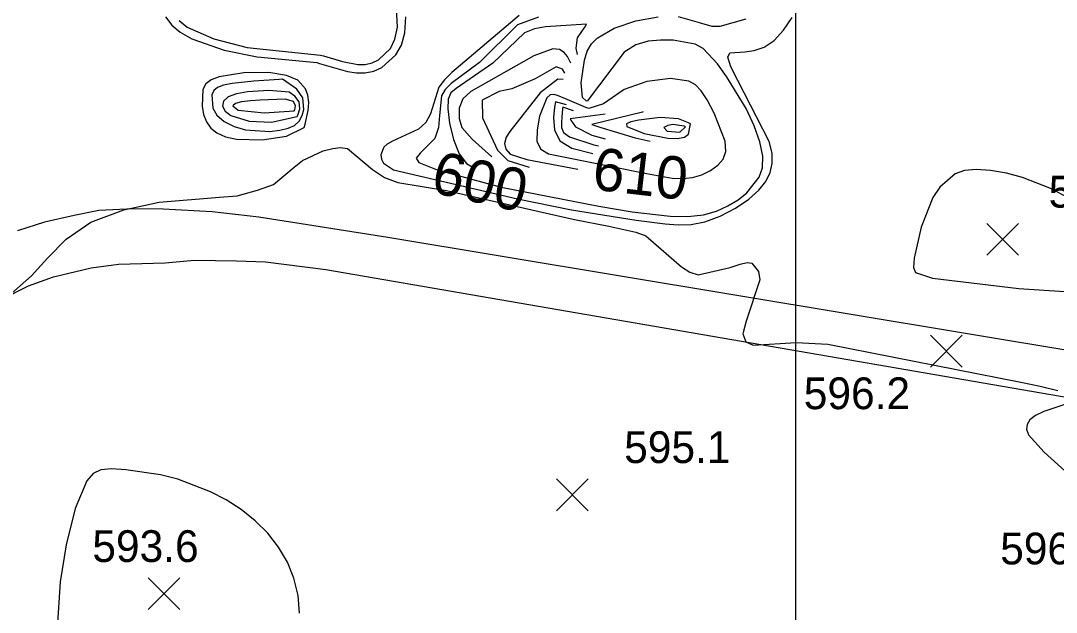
# Model space of a CAD drawing. Extents: x 79600 to 91800, y 75600 to 84400.
# Drawn here: x 86334.2 to 86823, y 76116.3 to 76395.7 of the extents above; entities that cross this region are included whole.
import ezdxf

# ---------------------------------------------------------------- set-up
doc = ezdxf.new("R2010")
doc.units = 0
for name, color, linetype in [('080-085$0$TI_BORDER', 7, 'Continuous'), ('080-090$0$INDEX', 7, 'Continuous'), ('080-090$0$INDXLBL', 7, 'Continuous'), ('080-090$0$INTER', 7, 'Continuous'), ('080-090$0$ROAD', 7, 'Continuous'), ('080-090$0$SPOTMARK', 7, 'Continuous'), ('080-090$0$SPOTS', 7, 'Continuous')]:
    doc.layers.add(name, color=color, linetype=linetype)

# ---------------------------------------------------------------- blocks, each defined once
blk = doc.blocks.new('080-090$0$SPOTS')
at = {"layer": '080-090$0$SPOTMARK'}
for p, q in [((-0.5, -0.5), (0.5, 0.5)), ((-0.5, 0.5), (0.5, -0.5))]:
    blk.add_line(p, q, dxfattribs=at)

msp = doc.modelspace()

# ---------------------------------------------------------------- linework, layer by layer
at = {"layer": '080-085$0$TI_BORDER'}
msp.add_lwpolyline([(79700, 80300), (86700, 80300), (86700, 75700), (79700, 75700)], close=True, dxfattribs=at)
at = {"layer": '080-090$0$INDEX'}
for points in [[(86409.09, 76395.76), (86412.88, 76392.65), (86425.34, 76387.09), (86441.16, 76382.97), (86475.78, 76379.44), (86477.09, 76379.04), (86486.19, 76376.41), (86493.34, 76375.07), (86496.78, 76375.06), (86500.07, 76375.74), (86503.19, 76377.17), (86508.79, 76382.62), (86510.89, 76386.93), (86512.08, 76392.59), (86511.37, 76407.51)], [(86578.64, 76397.37), (86568.81, 76393.78), (86550.85, 76376.01), (86537.41, 76365.95), (86534.61, 76363.24), (86532.89, 76360.14), (86531.86, 76350.9), (86531.39, 76345.2), (86529.73, 76339.99), (86522.85, 76333.07), (86520.95, 76330.76), (86522.12, 76328.71), (86530.79, 76325.21), (86561.1, 76317.03), (86607.15, 76308.07), (86622.85, 76305.48), (86640.74, 76303.38), (86649.21, 76303.22), (86656.5, 76304.06), (86662.7, 76305.79), (86668.07, 76308.21), (86672.82, 76311.14), (86676.92, 76314.46), (86682.87, 76321.85), (86684.35, 76326.25), (86684.49, 76331.68), (86683.1, 76338.42), (86680.37, 76346.1), (86676.59, 76354.18), (86667.46, 76369.38), (86663.2, 76375.37), (86656.4, 76382.63), (86652.62, 76384.54), (86642.24, 76386.41), (86636.29, 76386.51), (86630.35, 76386), (86624.57, 76384.34), (86619.05, 76380.89), (86601.69, 76357.7), (86601.19, 76357.83), (86599.42, 76359.38), (86598.8, 76366.4), (86600.35, 76377.06), (86601.69, 76381.34), (86603.59, 76384.7), (86606.29, 76387.47), (86614.43, 76392.11), (86624.64, 76395.58), (86635.14, 76397.57)], [(86644.59, 76397.63), (86654.46, 76394.8), (86660.39, 76393.07), (86664.42, 76393.11), (86676.63, 76396.53)]]:
    msp.add_lwpolyline(points, dxfattribs=at)
for points in [[(86456.18, 76367.95), (86444.2, 76367.19), (86434.11, 76365.98), (86429.99, 76365.16), (86427.1, 76364.17), (86425.32, 76362.77), (86424.4, 76360.7), (86424.86, 76354.4), (86426.84, 76351.01), (86430.33, 76348.05), (86435.01, 76345.71), (86440.41, 76344.12), (86451.61, 76343.37), (86456.52, 76343.91), (86460.47, 76344.85), (86463.49, 76346.26), (86465.68, 76348.25), (86467.15, 76350.83), (86467.91, 76353.74), (86467.36, 76359.2), (86464.6, 76363.4), (86457.83, 76367.99)], [(86600.92, 76354.74), (86592.18, 76358.4), (86587.59, 76360.37), (86585.84, 76360.79), (86584.2, 76360.61), (86582.57, 76359.23), (86579.15, 76350.55), (86577.94, 76344.21), (86577.92, 76338.59), (86579.67, 76334.94), (86583.34, 76332.8), (86613.99, 76326.67), (86629.6, 76323.44), (86641.77, 76321.33), (86646.75, 76321.09), (86651.36, 76321.6), (86655.77, 76322.96), (86659.82, 76324.99), (86663.25, 76327.47), (86665.79, 76330.29), (86667.08, 76333.86), (86666.76, 76338.73), (86661.52, 76352.08), (86658.2, 76358.24), (86655.37, 76362.62), (86652.71, 76365.4), (86649.63, 76367.07), (86640.9, 76368.32), (86629.75, 76366.92), (86619.07, 76363.23), (86609.36, 76356.49), (86602.34, 76354.19)], [(86649.39, 76347.49), (86644.75, 76349.39), (86636.12, 76350.02), (86626.08, 76348.73), (86622.24, 76347.9), (86620.11, 76346.94), (86620.4, 76345.68), (86628.51, 76342.4), (86639.65, 76340.13), (86644.22, 76339.98), (86647.58, 76340.66), (86649.51, 76342.13), (86650.35, 76346.92)]]:
    msp.add_lwpolyline(points, close=True, dxfattribs=at)
at = {"layer": '080-090$0$INTER'}
for points in [[(86402.6, 76397.57), (86405.51, 76393.63), (86409.54, 76390.21), (86415.04, 76387.13), (86430.25, 76381.81), (86445.78, 76378.65), (86474.02, 76375.93), (86475.27, 76375.5), (86488.48, 76371.64), (86492.68, 76371.04), (86496.86, 76371.05), (86500.9, 76371.87), (86504.7, 76373.54), (86511.37, 76379.51), (86513.9, 76384.07), (86515.53, 76390.02), (86516.06, 76397.49)], [(86569.58, 76398.12), (86537.8, 76371.25), (86534.28, 76367.81), (86531.6, 76364.35), (86527.59, 76351.63), (86525.54, 76347.56), (86521.97, 76344.38), (86509.75, 76338.75), (86507.26, 76337.42), (86505.59, 76335.97), (86504.3, 76332.31), (86504.6, 76330.33), (86505.54, 76328.43), (86510.2, 76325.17), (86568.8, 76311.5), (86594.26, 76306.31), (86624.79, 76301.52), (86638.46, 76299.77), (86644.6, 76299.26), (86650.68, 76299.42), (86657.18, 76300.71), (86664.36, 76303.41), (86671.57, 76307.14), (86677.9, 76311.35), (86682.65, 76315.58), (86685.91, 76319.78), (86687.96, 76323.98), (86689, 76328.3), (86688.94, 76333.05), (86687.6, 76338.58), (86672.78, 76367.43), (86669.44, 76373.85), (86667.94, 76378.39), (86668.93, 76380.49), (86675.98, 76380.99), (86680.5, 76381.56), (86685.18, 76383.21), (86689.85, 76386.33), (86694.32, 76391.15), (86698.34, 76397.13)], [(86597.13, 76379.67), (86596.41, 76382.67), (86597.02, 76387.64), (86600.56, 76392.68), (86601.24, 76394.11), (86581.92, 76392.72), (86576.74, 76391.86), (86572.05, 76389.99), (86557.04, 76375.63), (86539.79, 76363.68), (86537.22, 76361.54), (86535.99, 76358.67), (86535.88, 76354.11), (86536.71, 76347.31), (86538.46, 76339.62), (86541.12, 76332.83), (86544.67, 76328.29), (86547.27, 76326.61)], [(86593.98, 76375.61), (86592.34, 76378.77), (86590.79, 76380.73), (86588.52, 76382.14), (86585.39, 76382.39), (86576.51, 76379.12), (86546.63, 76362.29), (86542.86, 76358.84), (86541.15, 76354.35), (86541.18, 76349.5), (86542.44, 76345.25), (86547.27, 76339.8), (86556.59, 76331.37)], [(86591.08, 76370.87), (86589.92, 76372.79), (86587.03, 76373.88), (86577, 76368.17), (86565.98, 76363.57), (86560.06, 76362.23), (86552.02, 76358.16), (86552.28, 76349.83), (86559.27, 76334.53), (86564.1, 76329.69), (86574.17, 76326.56)], [(86590.32, 76367.86), (86587.82, 76368.07), (86579.48, 76361.61), (86565.16, 76343.29), (86563.35, 76340.6), (86562.67, 76337.73), (86563.28, 76334.97), (86565.25, 76332.67), (86573.14, 76330.06), (86597.16, 76325.49)], [(86591.82, 76355.9), (86586.6, 76357.42), (86586.2, 76354.78)], [(86586.2, 76354.78), (86585.73, 76349.98), (86586.17, 76344.19), (86588.76, 76338.95), (86594.32, 76335.41), (86604.35, 76333.03)], [(86590, 76354.03), (86589.61, 76350.12), (86589.45, 76347.65), (86589.52, 76345.2), (86590.52, 76342.88), (86593.23, 76340.77), (86604.83, 76337.09), (86606.92, 76336.59)], [(86595.22, 76353.15), (86590.14, 76354.92), (86590, 76354.03)], [(86628.06, 76352.57), (86627.7, 76352.54), (86603.75, 76346.65), (86607.65, 76345.33)], [(86610.13, 76351.57), (86593.61, 76349.34), (86593.83, 76348.63)], [(86593.83, 76348.63), (86596.04, 76345.56), (86603.88, 76341.6), (86610.11, 76339.87)], [(86607.65, 76345.33), (86624.35, 76340.39), (86631.37, 76338.79)], [(86317.81, 76256.21), (86339.39, 76275.16), (86346.88, 76283.57), (86355.66, 76292.52), (86367.4, 76300.49), (86382.92, 76306.29), (86399.52, 76309.97), (86428.03, 76312.33), (86436.45, 76313.03), (86445.96, 76315.58), (86453.51, 76318.28), (86463.28, 76326.46), (86467.28, 76329.64), (86477.01, 76334.16), (86481.58, 76335.39), (86485.25, 76335.87), (86488.43, 76335.28), (86500.36, 76325.45), (86505.93, 76321.68), (86512.31, 76319.25), (86535.19, 76315.48), (86595.67, 76301.79), (86611.84, 76298.56), (86624.66, 76295.75), (86629.26, 76294.09), (86646.22, 76279.49), (86650.07, 76276.85), (86653.99, 76275.61), (86669.1, 76279.07), (86673.78, 76280.75), (86677.11, 76281.51), (86679.36, 76281.2), (86682.44, 76277.22), (86683.07, 76273.33), (86676.59, 76253.81), (86675.1, 76247.8), (86676.44, 76244.08), (86679.97, 76242.38), (86700.26, 76243.77), (86715.29, 76242.98), (86806.27, 76224.97), (86815.51, 76223.02), (86823.78, 76221.04)], [(86832.97, 76309.59), (86820.8, 76316.21), (86807.16, 76321.61), (86799.56, 76323.6), (86792.01, 76324.92), (86785.24, 76325.41), (86779.78, 76324.91), (86775.38, 76323.38), (86768.06, 76317.12), (86764.78, 76312.18), (86759.31, 76298.09), (86756.02, 76283.53), (86755.58, 76279.19), (86756.52, 76276.69), (86764.58, 76274.06), (86805.38, 76269.22), (86846.15, 76266.52)], [(86834.93, 76217.01), (86817.23, 76211.16), (86813.17, 76209.2), (86810.61, 76207.15), (86809.26, 76205.01), (86808.96, 76202.76), (86809.97, 76200.07), (86817.37, 76191.94), (86837.01, 76174.08)], [(86465.89, 76115.78), (86465.15, 76124.26), (86463.2, 76132.36), (86460.11, 76140), (86455.95, 76147.1), (86450.85, 76153.63), (86444.94, 76159.52), (86438.36, 76164.75), (86431.28, 76169.31), (86423.85, 76173.21), (86408.35, 76179.07), (86400.19, 76181.14), (86383.85, 76183.63), (86377.1, 76183.96), (86372.09, 76183.51), (86368.42, 76181.81), (86365.43, 76178.32), (86359.95, 76165.35), (86355.63, 76148.17), (86352.88, 76130.65), (86350.75, 76098.97)]]:
    msp.add_lwpolyline(points, dxfattribs=at)
for points in [[(86468.49, 76346.78), (86469.91, 76353.26), (86470.18, 76357.09), (86469.71, 76360.56), (86468.59, 76363.5), (86465.09, 76367.56), (86459.72, 76369.78), (86451.28, 76371.21), (86439.54, 76371.02), (86427.91, 76369.1), (86424.06, 76367.73), (86421.62, 76365.86), (86420.27, 76363.19), (86419.84, 76355.39), (86420.57, 76351.32), (86421.87, 76347.84), (86423.91, 76344.99), (86426.89, 76342.68), (86430.98, 76340.89), (86436.05, 76339.67), (86448.27, 76339.39), (86459.69, 76341.21), (86468.04, 76345.21)], [(86465.11, 76351.12), (86466.02, 76354), (86465.65, 76357.37), (86463.67, 76360.05), (86460.94, 76361.85), (86451.4, 76362.71), (86441.22, 76362.03), (86436.13, 76361.16), (86432.14, 76359.73), (86429.91, 76357.66), (86429.47, 76355.25), (86430.68, 76352.88), (86433.37, 76350.88), (86442.03, 76348.29), (86452.58, 76347.71), (86464.8, 76350.43)], [(86463.61, 76353.55), (86464, 76355.54), (86463.01, 76357.56), (86459.13, 76358.55), (86447.3, 76358.13), (86442.66, 76357.79), (86438.52, 76357.31), (86435.55, 76356.58), (86434.32, 76355.54), (86436.81, 76353.35), (86449.12, 76352.17), (86463.37, 76353.05)], [(86647.43, 76345.85), (86642.12, 76346.62), (86639.64, 76346.11), (86637.77, 76345.25), (86639.31, 76343.53), (86645.32, 76343.05), (86648.09, 76345.59)]]:
    msp.add_lwpolyline(points, close=True, dxfattribs=at)
at = {"layer": '080-090$0$ROAD'}
for p, q in [((86359.45, 76303.72), (86345.41, 76300.47)), ((86371.12, 76306.03), (86359.45, 76303.72)), ((86387.61, 76306.89), (86371.12, 76306.03)), ((86401.46, 76306.67), (86387.61, 76306.89)), ((86424.56, 76305.35), (86401.46, 76306.67)), ((86446.68, 76302.93), (86424.56, 76305.35)), ((86345.41, 76300.47), (86332.75, 76296.51)), ((86507.6, 76293.27), (86446.68, 76302.93)), ((86952.93, 76219.27), (86507.6, 76293.27)), ((86349.73, 76274.65), (86367.52, 76278.95)), ((86367.52, 76278.95), (86380.42, 76280.69)), ((86380.42, 76280.69), (86402.45, 76281.32)), ((86402.45, 76281.32), (86416.32, 76282.63)), ((86416.32, 76282.63), (86436.12, 76282.32)), ((86436.12, 76282.32), (86449.82, 76281.84)), ((86449.82, 76281.84), (86478.29, 76278.21)), ((86337.89, 76270.4), (86349.73, 76274.65)), ((86478.29, 76278.21), (86946.92, 76197.34)), ((86325.19, 76263.95), (86337.89, 76270.4))]:
    msp.add_line(p, q, dxfattribs=at)

# ---------------------------------------------------------------- block references
at = {"layer": '080-090$0$SPOTMARK', "xscale": 15, "yscale": 15}
for p in [(86797.78, 76292.42), (86771.1, 76239.62), (86594.66, 76171.75), (86401.91, 76125.02)]:
    msp.add_blockref('080-090$0$SPOTS', p, dxfattribs=at)

# ---------------------------------------------------------------- texts
at = {"layer": '080-090$0$INDXLBL'}
for s, rotation, p in [('600', 347.3715, (86527.15, 76314.82)), ('610', 353.3701, (86603.5, 76316.06))]:
    msp.add_text(s, height=20, rotation=rotation, dxfattribs=at).set_placement(p)
at = {"layer": '080-090$0$SPOTS'}
for s, p in [('595.9', (86819.47, 76307.42)), ('596.2', (86703.85, 76212.21)), ('595.1', (86619.08, 76186.75)), ('593.6', (86368.04, 76140.02)), ('596.4', (86796.57, 76138.89))]:
    msp.add_text(s, height=15, dxfattribs=at).set_placement(p)

doc.saveas('drawing.dxf')
